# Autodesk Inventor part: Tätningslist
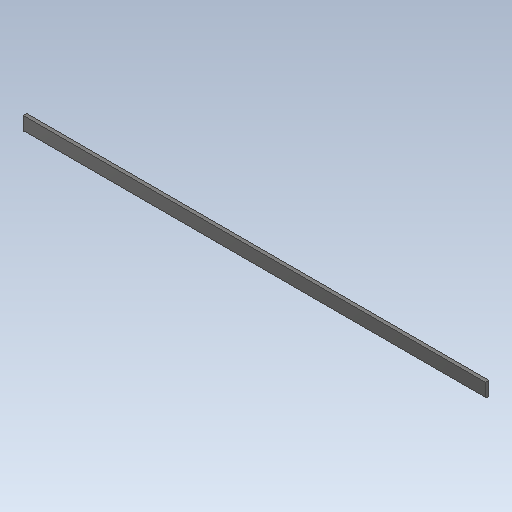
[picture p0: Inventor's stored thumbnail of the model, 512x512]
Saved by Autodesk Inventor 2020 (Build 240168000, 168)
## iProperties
Created: 2019-06
Part Number: Tätningslist
Material: Acetal Resin, Black
Document SubType Name: Modeling
Designer: cl
Density: 1.425 g/cm^3
Appearance: Smooth - Black
Author: cl
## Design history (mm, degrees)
sketch "Sketch1"
  geometry: L1 (4.9, 0)-(60, 0); L2 (60, 0)-(60, -14.8); L3 (60, -14.8)-(4.9, -14.8); L4 (0, -9.9)-(0, -4.9); A1 r 4.9 centre (4.9, -9.9) between (0, -9.9) and (4.9, -14.8); A2 r 4.9 centre (4.9, -4.9) between (4.9, 0) and (0, -4.9); 2 further points
  constraints: 8 end point, 4 point on circle, 4 point on line, 4 tangent, 2 centre point, 2 parallel, 1 equal radius, 1 horizontal, 1 perpendicular
  dimensions: "d0" = 60 distance of L2.end point (0, -14.8); "d1" = 14.8 distance of L1.end L2.end; "d2" = 4.9 radius of A1
extrude "Extrusion1" new body sketch "Sketch1" distance "d3" = 1970 (computed from Dagbredd); taper "d4" = 0 deg
body "Solid1"
